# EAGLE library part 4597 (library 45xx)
8-bit bus compatible COUNTER/LATCH
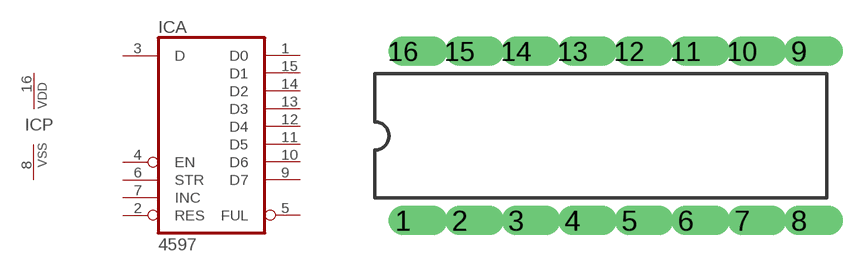
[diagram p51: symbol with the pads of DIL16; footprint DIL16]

Designator prefix IC; gates A=4597 P=PWRN

## 4597N  [DIL16]
1  A:D0  out
2  A:RES  in
3  A:D  in
4  A:EN  in
5  A:FUL  out
6  A:STR  in
7  A:INC  in
8  P:VSS  pwr
9  A:D7  out
10  A:D6  out
11  A:D5  out
12  A:D4  out
13  A:D3  out
14  A:D2  out
15  A:D1  out
16  P:VDD  pwr

## Footprint DIL16 (pad centres in mm)
Dual In Line
drill 0.813 offset: 1 -8.89,-3.81; 2 -6.35,-3.81; 3 -3.81,-3.81; 4 -1.27,-3.81; 5 1.27,-3.81; 6 3.81,-3.81; 7 6.35,-3.81; 8 8.89,-3.81; 9 8.89,3.81; 10 6.35,3.81; 11 3.81,3.81; 12 1.27,3.81; 13 -1.27,3.81; 14 -3.81,3.81; 15 -6.35,3.81; 16 -8.89,3.81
